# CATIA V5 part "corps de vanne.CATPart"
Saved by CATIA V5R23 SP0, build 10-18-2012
Part number: corps de vanne
Definition: corps de vanne
Source: made
Bounding box of the stored display mesh (mm): x 60 to 135, y -76 to 76, z -76 to 76
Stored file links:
  C:\wamp\www\COURS\CONCEPTION GMP1\TITRE 01-CATIA VOLUMIQUE\05--ACTIONNEUR DE VANNE\prof\CORRECTION\Assemblage\corps de vanne.CATPart
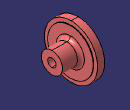
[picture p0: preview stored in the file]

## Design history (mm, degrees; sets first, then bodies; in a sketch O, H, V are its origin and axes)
Body1 "NONE" (main body)
  Solid1 "Manifold Solid #2957": solid without history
